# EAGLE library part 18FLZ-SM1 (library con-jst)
CONNECTOR
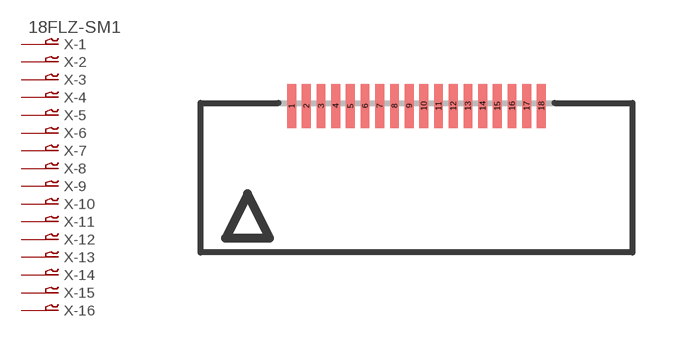
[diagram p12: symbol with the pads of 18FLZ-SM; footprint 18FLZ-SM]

Designator prefix X; gates -1=P-VN -2=P-N -3=P-N -4=P-N -5=P-N -6=P-N -7=P-N -8=P-N -9=P-N -10=P-N -11=P-N -12=P-N -13=P-N -14=P-N -15=P-N -16=P-N -17=P-N -18=P-N

## 18FLZ-SM1 (OC_FARNELL: unknown; OC_NEWARK: unknown)  [18FLZ-SM]
1  -1:1  pas
2  -2:1  pas
3  -3:1  pas
4  -4:1  pas
5  -5:1  pas
6  -6:1  pas
7  -7:1  pas
8  -8:1  pas
9  -9:1  pas
10  -10:1  pas
11  -11:1  pas
12  -12:1  pas
13  -13:1  pas
14  -14:1  pas
15  -15:1  pas
16  -16:1  pas
17  -17:1  pas
18  -18:1  pas

## Footprint 18FLZ-SM (pad centres in mm)
CONNECTOR
smd 0.3 x 1.5: 1 -4.25,2.5; 2 -3.75,2.5; 3 -3.25,2.5; 4 -2.75,2.5; 5 -2.25,2.5; 6 -1.75,2.5; 7 -1.25,2.5; 8 -0.75,2.5; 9 -0.25,2.5; 10 0.25,2.5; 11 0.75,2.5; 12 1.25,2.5; 13 1.75,2.5; 14 2.25,2.5; 15 2.75,2.5; 16 3.25,2.5; 17 3.75,2.5; 18 4.25,2.5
